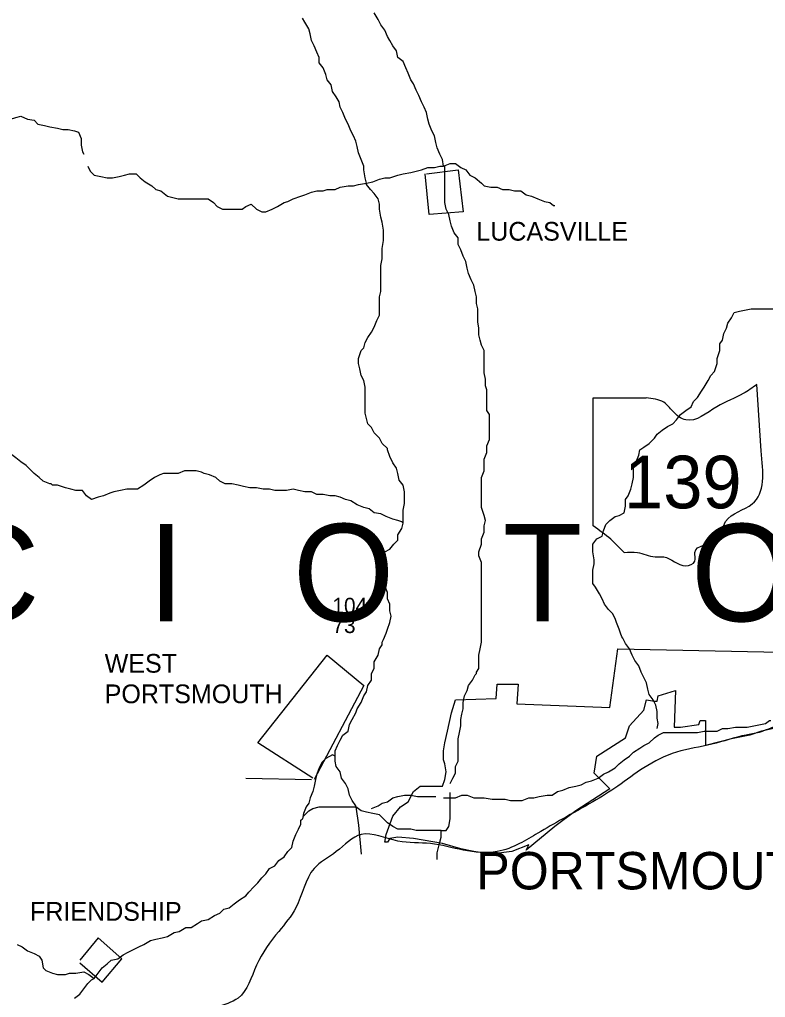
# Model space of a CAD drawing. Extents: x 0 to 34, y 0 to 22.
# Drawn here: x 5.61 to 6.387, y 16.176 to 17.195 of the extents above; entities that cross this region are included whole.
import ezdxf

# ---------------------------------------------------------------- set-up
doc = ezdxf.new("R2010")
doc.units = 0
doc.layers.add('Default', color=7, linetype='Continuous')
doc.layers.add('TR_Turning_Path1', color=7, linetype='Continuous')

msp = doc.modelspace()

# ---------------------------------------------------------------- linework, layer by layer
at = {"layer": 'Default'}
msp.add_line((5.8454, 16.4046), (5.9136, 16.4032), dxfattribs=at)
for points in [[(5.9654, 17.0495), (5.9627, 17.0563), (5.9613, 17.0631), (5.96, 17.0686), (5.9573, 17.074), (5.9545, 17.0795), (5.9518, 17.0863), (5.9491, 17.0917), (5.9463, 17.0985), (5.9436, 17.104), (5.9423, 17.1095), (5.9395, 17.1149), (5.9354, 17.1204), (5.9341, 17.1272), (5.93, 17.1326), (5.9286, 17.1381), (5.9259, 17.1449), (5.9218, 17.1504), (5.9218, 17.1558), (5.9191, 17.1613), (5.9163, 17.1681), (5.9136, 17.1735), (5.9123, 17.1804), (5.9109, 17.1858), (5.9068, 17.1926), (5.9041, 17.1967)], [(6.0513, 17.0426), (6.05, 17.0495), (6.0472, 17.0549), (6.0445, 17.0617), (6.0431, 17.0672), (6.0418, 17.074), (6.0391, 17.0795), (6.0363, 17.0863), (6.035, 17.0917), (6.0336, 17.0985), (6.0309, 17.104), (6.0281, 17.1095), (6.0254, 17.1163), (6.0227, 17.1217), (6.02, 17.1285), (6.0172, 17.1326), (6.0145, 17.1395), (6.0118, 17.1449), (6.0091, 17.1517), (6.0036, 17.1558), (6.0022, 17.1626), (5.9982, 17.1681), (5.9954, 17.1735), (5.9927, 17.1776), (5.99, 17.1844), (5.9859, 17.1899), (5.9832, 17.1954), (5.9791, 17.2022)], [(5.5809, 17.0904), (5.5864, 17.0904), (5.5932, 17.0904), (5.6, 17.0917), (5.6055, 17.0931), (5.6109, 17.0945), (5.6178, 17.0917), (5.6246, 17.0904), (5.6287, 17.0863), (5.6355, 17.0849), (5.6409, 17.0836), (5.6491, 17.0822), (5.6546, 17.0808), (5.66, 17.0808), (5.6668, 17.0795), (5.6709, 17.0781), (5.6737, 17.0713), (5.6737, 17.0645), (5.675, 17.0576), (5.6764, 17.0549), (5.6764, 17.0549)], [(5.6805, 17.0426), (5.6832, 17.0372), (5.6873, 17.0331), (5.6941, 17.0317), (5.7009, 17.0304), (5.7064, 17.0304), (5.7132, 17.0317), (5.7187, 17.0331), (5.7241, 17.0345), (5.7309, 17.0345), (5.735, 17.0304), (5.7405, 17.0263), (5.7473, 17.0222), (5.7514, 17.0181), (5.7568, 17.0167), (5.7636, 17.0113), (5.7691, 17.0099), (5.7746, 17.0086), (5.7814, 17.0086), (5.7882, 17.0086), (5.7936, 17.0086), (5.7991, 17.0086), (5.8059, 17.0086), (5.8114, 17.0045), (5.8155, 17.0004), (5.8209, 16.9977), (5.8277, 16.9977)], [(5.9709, 17.0249), (5.9695, 17.0304), (5.9682, 17.0386), (5.9682, 17.0426), (5.9654, 17.0495), (5.9654, 17.0495)], [(5.9709, 17.0249), (5.9777, 17.0263), (5.9845, 17.029), (5.99, 17.0304), (5.9954, 17.0304), (6.0036, 17.0331), (6.0091, 17.0345), (6.0172, 17.0358), (6.0227, 17.0372), (6.0281, 17.0386), (6.035, 17.0413), (6.0418, 17.0413), (6.0472, 17.0426), (6.0513, 17.0426)], [(6.0513, 17.0426), (6.0581, 17.0454), (6.0636, 17.0454), (6.0691, 17.0413), (6.0745, 17.0386), (6.0786, 17.0331), (6.084, 17.0304), (6.0909, 17.0249), (6.0936, 17.0222), (6.1004, 17.0208), (6.1072, 17.0208), (6.1127, 17.0181), (6.1195, 17.0181), (6.125, 17.0167), (6.1318, 17.0167), (6.1372, 17.0127), (6.1427, 17.0113), (6.1495, 17.0086), (6.1563, 17.0058), (6.1618, 17.0045), (6.1659, 17.0017), (6.1672, 17.0017)], [(6.0936, 16.8436), (6.0936, 16.8504), (6.0909, 16.8559), (6.0895, 16.8613), (6.0881, 16.8668), (6.0881, 16.8736), (6.0868, 16.8804), (6.0868, 16.8872), (6.0868, 16.894), (6.0854, 16.8995), (6.0854, 16.9063), (6.084, 16.9118), (6.0827, 16.9186), (6.08, 16.924), (6.0772, 16.9308), (6.0759, 16.9363), (6.0745, 16.9431), (6.0718, 16.9486), (6.0691, 16.9554), (6.0663, 16.9608), (6.0663, 16.9677), (6.0622, 16.9731), (6.0595, 16.9799), (6.0581, 16.9854), (6.0568, 16.9922), (6.0541, 16.9977), (6.0527, 17.0045), (6.0527, 17.0086), (6.0527, 17.0167), (6.0527, 17.0222), (6.0527, 17.029), (6.0527, 17.0358), (6.0527, 17.0413), (6.0527, 17.0426), (6.0513, 17.0426)], [(6.0336, 17.0345), (6.0663, 17.0386), (6.0718, 16.9949), (6.0363, 16.9922), (6.0322, 17.0345)], [(5.8277, 16.9977), (5.8332, 16.9977), (5.8414, 16.9977), (5.8454, 17.0004), (5.8509, 17.0031), (5.8564, 16.9977), (5.8618, 16.9949), (5.8659, 16.9949), (5.8727, 16.9977), (5.8782, 17.0004), (5.885, 17.0045), (5.8891, 17.0058), (5.8945, 17.0086), (5.9027, 17.0113), (5.9068, 17.0127), (5.9136, 17.0154), (5.9191, 17.0167), (5.9259, 17.0167), (5.93, 17.0181), (5.9382, 17.0181), (5.9436, 17.0208), (5.9518, 17.0222), (5.9573, 17.0222), (5.9627, 17.0236), (5.9709, 17.0249), (5.9709, 17.0249)], [(5.9682, 16.8531), (5.9695, 16.8586), (5.9722, 16.864), (5.9763, 16.8695), (5.9791, 16.8749), (5.9818, 16.8818), (5.9845, 16.8872), (5.9845, 16.894), (5.9845, 16.8995), (5.9845, 16.9063), (5.9859, 16.9118), (5.9859, 16.9186), (5.9859, 16.9254), (5.9859, 16.9322), (5.9859, 16.939), (5.9872, 16.9458), (5.9872, 16.9513), (5.9872, 16.9568), (5.9886, 16.9649), (5.9886, 16.9718), (5.9886, 16.9758), (5.9872, 16.984), (5.9859, 16.9895), (5.9845, 16.9977), (5.9845, 17.0031), (5.9832, 17.0086), (5.9791, 17.014), (5.975, 17.0181), (5.9709, 17.0236), (5.9709, 17.0249), (5.9709, 17.0249)], [(6.3363, 16.8368), (6.3363, 16.8422), (6.339, 16.8504), (6.339, 16.8572), (6.3417, 16.8613), (6.3431, 16.8681), (6.3458, 16.8736), (6.3472, 16.879), (6.3513, 16.8845), (6.354, 16.8899), (6.3595, 16.8913), (6.3663, 16.8927), (6.3717, 16.894), (6.3785, 16.894), (6.3854, 16.894), (6.3908, 16.894), (6.3963, 16.894), (6.4031, 16.8913), (6.4072, 16.8886), (6.4126, 16.8872), (6.4126, 16.8872)], [(5.9927, 16.7481), (5.9872, 16.7536), (5.9845, 16.7591), (5.9791, 16.7645), (5.9763, 16.77), (5.9722, 16.7741), (5.9709, 16.7795), (5.9695, 16.785), (5.9695, 16.7931), (5.9695, 16.8), (5.9695, 16.8054), (5.9695, 16.8122), (5.9682, 16.819), (5.9654, 16.8245), (5.9641, 16.8313), (5.9627, 16.8368), (5.9627, 16.8422), (5.9654, 16.8504), (5.9682, 16.8531)], [(6.0909, 16.6868), (6.0909, 16.6936), (6.0909, 16.6991), (6.0909, 16.7059), (6.0909, 16.7113), (6.0909, 16.7182), (6.0936, 16.725), (6.0936, 16.7304), (6.0936, 16.7372), (6.0963, 16.7441), (6.0963, 16.7509), (6.099, 16.7577), (6.099, 16.7631), (6.099, 16.7686), (6.099, 16.7768), (6.099, 16.7836), (6.0963, 16.7877), (6.0963, 16.7959), (6.0963, 16.8013), (6.0963, 16.8095), (6.095, 16.8136), (6.095, 16.8204), (6.0936, 16.8272), (6.0936, 16.834), (6.0936, 16.8409), (6.0936, 16.8422), (6.0936, 16.8436)], [(6.2517, 16.7345), (6.2545, 16.7413), (6.2558, 16.7468), (6.2599, 16.7495), (6.2654, 16.7536), (6.2708, 16.7591), (6.2736, 16.7631), (6.279, 16.7672), (6.2845, 16.7713), (6.2899, 16.7741), (6.294, 16.7781), (6.2981, 16.7836), (6.3036, 16.7877), (6.309, 16.7918), (6.3117, 16.7972), (6.3158, 16.8013), (6.3199, 16.8081), (6.3226, 16.8122), (6.3267, 16.819), (6.3295, 16.8245), (6.3336, 16.8286), (6.3363, 16.8368), (6.3363, 16.8368)], [(6.382, 16.7458), (6.3774, 16.8148)], [(6.2071, 16.6675), (6.2071, 16.801), (6.2623, 16.801)], [(5.6437, 16.71), (5.6423, 16.7113), (5.6409, 16.7113), (5.6341, 16.7141), (5.63, 16.7182), (5.6246, 16.7222), (5.6205, 16.7263), (5.6164, 16.7304), (5.6109, 16.7345), (5.6055, 16.7386), (5.6, 16.7427), (5.5946, 16.7468), (5.5905, 16.7481), (5.5837, 16.7522), (5.5782, 16.7536), (5.5728, 16.7563), (5.5673, 16.7604)], [(6.0091, 16.6704), (6.0091, 16.6773), (6.0091, 16.6841), (6.0104, 16.6909), (6.0104, 16.6977), (6.0104, 16.7032), (6.0091, 16.71), (6.005, 16.7154), (6.0036, 16.7222), (6.0022, 16.7277), (5.9982, 16.7332), (5.9954, 16.74), (5.9927, 16.7468), (5.9927, 16.7468), (5.9927, 16.7481)], [(6.2068, 16.6486), (6.2108, 16.6541), (6.2163, 16.6568), (6.2177, 16.6623), (6.2204, 16.6691), (6.2245, 16.6732), (6.2299, 16.6773), (6.234, 16.6786), (6.2395, 16.6813), (6.2408, 16.6882), (6.2408, 16.695), (6.2436, 16.6991), (6.2463, 16.7059), (6.2477, 16.7113), (6.249, 16.7182), (6.249, 16.7222), (6.249, 16.7304), (6.2517, 16.7332), (6.2517, 16.7345)], [(5.8018, 16.7222), (5.8018, 16.7222), (5.7991, 16.7236), (5.7936, 16.725), (5.7868, 16.725), (5.7814, 16.725), (5.7746, 16.7222), (5.7664, 16.7222), (5.7596, 16.7222), (5.7555, 16.7209), (5.75, 16.7182), (5.7446, 16.7141), (5.7391, 16.71), (5.7323, 16.7059), (5.7268, 16.7059), (5.7214, 16.7059), (5.7146, 16.7045), (5.7077, 16.7032), (5.7037, 16.7018), (5.6968, 16.6991), (5.6914, 16.6977), (5.6846, 16.695), (5.6791, 16.6991), (5.675, 16.7045), (5.6682, 16.7045), (5.6628, 16.7059), (5.6573, 16.7072), (5.6491, 16.71), (5.6437, 16.71)], [(6.0091, 16.6704), (6.0077, 16.6718), (6.0036, 16.6732), (5.9982, 16.6745), (5.9913, 16.6773), (5.9859, 16.68), (5.9791, 16.6813), (5.9736, 16.6854), (5.9682, 16.6868), (5.9613, 16.6895), (5.9545, 16.6936), (5.9491, 16.695), (5.9436, 16.6977), (5.9382, 16.6991), (5.9327, 16.6991), (5.9259, 16.7004), (5.9191, 16.7004), (5.9136, 16.7032), (5.9068, 16.7032), (5.9, 16.7045), (5.8945, 16.7059), (5.8877, 16.7045), (5.8809, 16.7045), (5.8754, 16.7045), (5.87, 16.7059), (5.8632, 16.7059), (5.8564, 16.7072), (5.8495, 16.7072), (5.8427, 16.7086), (5.8373, 16.71), (5.8305, 16.7113), (5.8236, 16.7113), (5.8182, 16.7141), (5.8141, 16.7182), (5.8073, 16.7209), (5.8018, 16.7222)], [(6.0854, 16.515), (6.0881, 16.5191), (6.0881, 16.5259), (6.0881, 16.5327), (6.0895, 16.5395), (6.0909, 16.5464), (6.0909, 16.5518), (6.0909, 16.5586), (6.0909, 16.5641), (6.0909, 16.5709), (6.0909, 16.5777), (6.0909, 16.5832), (6.0909, 16.5914), (6.0909, 16.5968), (6.0909, 16.6036), (6.0909, 16.6077), (6.0909, 16.6159), (6.0909, 16.6214), (6.0909, 16.6295), (6.0881, 16.6363), (6.0881, 16.6404), (6.0909, 16.6486), (6.0909, 16.6541), (6.0936, 16.6609), (6.0936, 16.6677), (6.095, 16.6732), (6.0936, 16.6786), (6.0909, 16.6868)], [(5.9872, 16.5436), (5.9872, 16.5464), (5.9886, 16.5491), (5.9913, 16.5559), (5.9927, 16.56), (5.9954, 16.5668), (5.9968, 16.5736), (5.9954, 16.5791), (5.9954, 16.5859), (5.9927, 16.5914), (5.9927, 16.5982), (5.99, 16.605), (5.9886, 16.6104), (5.9872, 16.6159), (5.9859, 16.6227), (5.9859, 16.6295), (5.9859, 16.6363), (5.99, 16.6404), (5.9954, 16.6432), (5.9995, 16.6486), (6.0036, 16.6527), (6.0036, 16.6582), (6.0077, 16.665), (6.0091, 16.6704)], [(5.9872, 16.5436), (5.9872, 16.5464), (5.9886, 16.5491), (5.9913, 16.5559), (5.9927, 16.56), (5.9954, 16.5668), (5.9968, 16.5736), (5.9954, 16.5791), (5.9954, 16.5859), (5.9927, 16.5914), (5.9927, 16.5982), (5.99, 16.605), (5.9886, 16.6104), (5.9872, 16.6159), (5.9859, 16.6227), (5.9859, 16.6295), (5.9859, 16.6363), (5.99, 16.6404), (5.9954, 16.6432), (5.9995, 16.6486), (6.0036, 16.6527), (6.0036, 16.6582), (6.0077, 16.665), (6.0091, 16.6704)], [(6.2354, 16.5559), (6.234, 16.56), (6.2313, 16.5668), (6.2299, 16.5709), (6.2272, 16.5764), (6.2231, 16.5804), (6.219, 16.5859), (6.2163, 16.5914), (6.2136, 16.5968), (6.2095, 16.6036), (6.2068, 16.6077), (6.2068, 16.6145), (6.2068, 16.6214), (6.2081, 16.6282), (6.2081, 16.6323), (6.2068, 16.6404), (6.2068, 16.6459), (6.2068, 16.6486)], [(6.2736, 16.4564), (6.2749, 16.4618), (6.2736, 16.4673), (6.2736, 16.4741), (6.2722, 16.4809), (6.2695, 16.4864), (6.2654, 16.4918), (6.264, 16.4973), (6.2627, 16.5041), (6.2599, 16.5096), (6.2572, 16.515), (6.2545, 16.5218), (6.2504, 16.5273), (6.2477, 16.5327), (6.2449, 16.5395), (6.2408, 16.545), (6.2381, 16.5505), (6.2368, 16.5518), (6.2354, 16.5559)], [(5.9382, 16.4277), (5.9382, 16.4291), (5.9382, 16.4332), (5.9409, 16.4387), (5.9436, 16.4441), (5.9463, 16.4496), (5.9518, 16.4537), (5.9532, 16.4605), (5.9559, 16.4659), (5.96, 16.4727), (5.9613, 16.4768), (5.9654, 16.4836), (5.9682, 16.4905), (5.9709, 16.4946), (5.9722, 16.5014), (5.9763, 16.5068), (5.9763, 16.5136), (5.9791, 16.5191), (5.9791, 16.5259), (5.9832, 16.5327), (5.9845, 16.5395), (5.9872, 16.5436)], [(5.9382, 16.4277), (5.9382, 16.4291), (5.9382, 16.4332), (5.9409, 16.4387), (5.9436, 16.4441), (5.9463, 16.4496), (5.9518, 16.4537), (5.9532, 16.4605), (5.9559, 16.4659), (5.96, 16.4727), (5.9613, 16.4768), (5.9654, 16.4836), (5.9682, 16.4905), (5.9709, 16.4946), (5.9722, 16.5014), (5.9763, 16.5068), (5.9763, 16.5136), (5.9791, 16.5191), (5.9791, 16.5259), (5.9832, 16.5327), (5.9845, 16.5395), (5.9872, 16.5436)], [(5.915, 16.4046), (5.8577, 16.4414), (5.93, 16.5327), (5.9682, 16.5014), (5.9163, 16.4032)], [(5.9913, 16.3459), (5.9982, 16.365), (6.0063, 16.3746), (6.0145, 16.38), (6.02, 16.3909), (6.0268, 16.3964), (6.05, 16.3964), (6.0527, 16.4032), (6.0541, 16.4114), (6.0527, 16.4196), (6.0513, 16.4237), (6.0513, 16.4332), (6.0527, 16.4414), (6.0554, 16.4537), (6.0595, 16.4727), (6.0636, 16.4864), (6.1059, 16.4877), (6.1072, 16.5027), (6.129, 16.5027), (6.1277, 16.4823), (6.2245, 16.4782), (6.2327, 16.5395), (6.4863, 16.5341)], [(6.0663, 16.4264), (6.0663, 16.4332), (6.0663, 16.44), (6.0663, 16.4455), (6.0677, 16.4523), (6.0691, 16.4591), (6.0691, 16.4659), (6.0704, 16.4714), (6.0718, 16.4768), (6.0718, 16.4836), (6.0731, 16.4905), (6.0759, 16.4959), (6.0772, 16.5014), (6.0813, 16.5068), (6.084, 16.5123), (6.0854, 16.5136), (6.0854, 16.515)], [(6.2245, 16.3937), (6.2081, 16.41), (6.2108, 16.4277), (6.2408, 16.4468), (6.2449, 16.4591), (6.2599, 16.4755), (6.2627, 16.4864), (6.2708, 16.485), (6.2736, 16.485), (6.2749, 16.4905), (6.2927, 16.4959), (6.2913, 16.4577), (6.2981, 16.4577), (6.3172, 16.4605), (6.3186, 16.4646), (6.324, 16.4646), (6.324, 16.4387)], [(6.3036, 16.4523), (6.309, 16.4523), (6.3158, 16.4523), (6.3226, 16.4537), (6.3295, 16.4537), (6.3363, 16.4537), (6.3417, 16.4564), (6.3472, 16.4564), (6.3554, 16.4577), (6.3608, 16.4577), (6.3676, 16.4577), (6.3745, 16.4591), (6.3813, 16.4605), (6.3867, 16.4618), (6.3908, 16.4646), (6.3922, 16.4646)], [(6.1822, 16.395), (6.189, 16.3964), (6.1945, 16.3977), (6.1999, 16.4005), (6.2054, 16.4018), (6.2122, 16.4046), (6.2177, 16.4087), (6.2231, 16.4114), (6.2299, 16.4155), (6.234, 16.4196), (6.2395, 16.4237), (6.2449, 16.4277), (6.249, 16.4318), (6.2558, 16.4359), (6.2599, 16.4387), (6.2654, 16.4414), (6.2708, 16.4468), (6.2749, 16.4496), (6.2804, 16.4523), (6.2804, 16.4523)], [(6.2804, 16.4523), (6.2872, 16.4523), (6.294, 16.4523), (6.3008, 16.4523), (6.3036, 16.4523)], [(6.414, 16.4605), (6.3826, 16.4537), (6.3704, 16.4496), (6.3513, 16.4455), (6.324, 16.4387)], [(5.9382, 16.4277), (5.9382, 16.4277), (5.9354, 16.4291), (5.9286, 16.425), (5.9245, 16.4209), (5.9218, 16.4155), (5.9191, 16.4087), (5.9177, 16.4032), (5.9163, 16.3964), (5.915, 16.3909), (5.9123, 16.3841), (5.9109, 16.3787)], [(5.96, 16.3746), (5.96, 16.3759), (5.9559, 16.3814), (5.9532, 16.3868), (5.9518, 16.3937), (5.9491, 16.3991), (5.945, 16.4046), (5.9436, 16.4114), (5.9395, 16.4168), (5.9382, 16.4223), (5.9382, 16.4277)], [(5.96, 16.3746), (5.96, 16.3759), (5.9559, 16.3814), (5.9532, 16.3868), (5.9518, 16.3937), (5.9491, 16.3991), (5.945, 16.4046), (5.9436, 16.4114), (5.9395, 16.4168), (5.9382, 16.4223), (5.9382, 16.4277)], [(6.0581, 16.3991), (6.0609, 16.4046), (6.0636, 16.41), (6.0636, 16.4168), (6.0663, 16.4223), (6.0663, 16.4264)], [(6.2245, 16.3937), (6.189, 16.3705), (6.1672, 16.3541), (6.1372, 16.3296), (6.1399, 16.335), (6.1222, 16.3282), (6.1004, 16.3255), (6.0827, 16.3282), (6.0691, 16.3309), (6.05, 16.3364), (6.02, 16.3418), (6.0036, 16.3432), (5.9954, 16.3418), (5.9927, 16.3378)], [(6.1454, 16.3841), (6.1509, 16.3855), (6.159, 16.3868), (6.1645, 16.3868), (6.1699, 16.3909), (6.1754, 16.3923), (6.1822, 16.395)], [(5.9763, 16.3732), (5.9832, 16.3759), (5.9872, 16.3787), (5.9927, 16.38), (5.9982, 16.3841), (6.0036, 16.3855), (6.0104, 16.3868), (6.0172, 16.3868), (6.0241, 16.3855), (6.0295, 16.3855), (6.0363, 16.3855), (6.0418, 16.3855), (6.0431, 16.3855)], [(6.0486, 16.35), (6.0541, 16.35), (6.0568, 16.3541), (6.0581, 16.3623), (6.0581, 16.3678), (6.0581, 16.3746), (6.0581, 16.38), (6.0581, 16.3841)], [(6.0513, 16.3841), (6.0581, 16.3841), (6.0581, 16.3841)], [(6.0581, 16.3841), (6.0581, 16.3896)], [(6.0581, 16.3841), (6.0636, 16.3841), (6.0704, 16.3868), (6.0759, 16.3868), (6.0827, 16.3841), (6.0881, 16.3841), (6.0936, 16.3841), (6.1018, 16.3828), (6.1072, 16.3828), (6.1154, 16.3828), (6.1209, 16.3814), (6.1277, 16.3814), (6.1331, 16.3814), (6.1399, 16.3841), (6.1427, 16.3841), (6.1454, 16.3841)], [(5.9109, 16.3787), (5.9082, 16.3746), (5.9054, 16.3678), (5.9041, 16.3623)], [(5.9054, 16.365), (5.9109, 16.3705), (5.915, 16.3732), (5.9218, 16.3746), (5.9286, 16.3746), (5.9354, 16.3746), (5.9395, 16.3746), (5.9463, 16.3746), (5.9532, 16.3746), (5.96, 16.3746), (5.96, 16.3746)], [(6.0486, 16.35), (6.0472, 16.35), (6.0431, 16.35), (6.0363, 16.35), (6.0295, 16.35), (6.0227, 16.35), (6.0172, 16.3514), (6.0104, 16.3514), (6.0036, 16.3514), (5.9982, 16.3541), (5.9927, 16.3582), (5.9886, 16.3623), (5.9845, 16.3664), (5.9777, 16.3678), (5.9709, 16.3691), (5.9654, 16.3705), (5.96, 16.3746)], [(6.0486, 16.35), (6.0472, 16.35), (6.0431, 16.35), (6.0363, 16.35), (6.0295, 16.35), (6.0227, 16.35), (6.0172, 16.3514), (6.0104, 16.3514), (6.0036, 16.3514), (5.9982, 16.3541), (5.9927, 16.3582), (5.9886, 16.3623), (5.9845, 16.3664), (5.9777, 16.3678), (5.9709, 16.3691), (5.9654, 16.3705), (5.96, 16.3746)], [(5.96, 16.3746), (5.9627, 16.3555), (5.9654, 16.3255)], [(5.7991, 16.256), (5.8059, 16.2573), (5.8127, 16.2614), (5.8182, 16.2641), (5.8223, 16.2682), (5.8277, 16.2696), (5.8332, 16.2737), (5.8386, 16.2778), (5.8454, 16.2819), (5.8482, 16.2859), (5.8536, 16.2914), (5.8577, 16.2955), (5.8618, 16.3009), (5.8659, 16.305), (5.87, 16.3105), (5.8754, 16.3132), (5.8795, 16.3187), (5.885, 16.3228), (5.8891, 16.3282), (5.8932, 16.3323), (5.8945, 16.3391), (5.8973, 16.3459), (5.9, 16.3514), (5.9027, 16.3568), (5.9027, 16.3609), (5.9041, 16.3623)], [(6.0472, 16.3378), (6.0486, 16.3432), (6.0486, 16.35)], [(5.9927, 16.3378), (5.99, 16.3378), (5.9913, 16.3459)], [(6.0445, 16.32), (6.0445, 16.3269), (6.0459, 16.3323), (6.0472, 16.3378), (6.0472, 16.3378)], [(5.6873, 16.196), (5.6914, 16.2014), (5.6955, 16.2069), (5.7009, 16.211), (5.705, 16.2151), (5.7118, 16.2164), (5.7173, 16.2205), (5.7227, 16.2232), (5.7282, 16.226), (5.7336, 16.2287), (5.7391, 16.2314), (5.7459, 16.2355), (5.7514, 16.2369), (5.7582, 16.2382), (5.7636, 16.2396), (5.7705, 16.2437), (5.7759, 16.245), (5.7827, 16.2491), (5.7882, 16.2491), (5.795, 16.2532), (5.7991, 16.256), (5.7991, 16.256)], [(5.6723, 16.2123), (5.6955, 16.1919), (5.7159, 16.2164), (5.6914, 16.2382), (5.6723, 16.2151)], [(5.6069, 16.2314), (5.6123, 16.2287), (5.6178, 16.2246), (5.6246, 16.2219), (5.63, 16.2191), (5.6328, 16.2151), (5.6341, 16.2069), (5.6368, 16.2041), (5.6437, 16.2014), (5.6491, 16.2001), (5.6573, 16.2001), (5.6614, 16.2014), (5.6682, 16.2014), (5.6764, 16.2028), (5.6818, 16.2001), (5.6873, 16.196)], [(5.6668, 16.1755), (5.6723, 16.1796), (5.6764, 16.1851), (5.6805, 16.1905), (5.6846, 16.1946), (5.6873, 16.196), (5.6873, 16.196)]]:
    msp.add_lwpolyline(points, dxfattribs=at)
for points in [[(6.3774, 16.8148), (6.3635, 16.8056), (6.3359, 16.7918), (6.3037, 16.778), (6.2899, 16.7872), (6.2807, 16.7964), (6.2623, 16.801)], [(6.2393, 16.6399), (6.2531, 16.6399), (6.2715, 16.6353), (6.2807, 16.6353), (6.3037, 16.6261), (6.3129, 16.6307), (6.3129, 16.6399), (6.3359, 16.6537), (6.3451, 16.6721), (6.3728, 16.6905), (6.382, 16.7458)], [(6.2393, 16.6399), (6.2255, 16.6537), (6.2071, 16.6675)], [(6.6853, 15.6179), (6.6553, 15.637), (6.6308, 15.656), (6.5994, 15.6806), (6.579, 15.7174), (6.5653, 15.7529), (6.5531, 15.7842), (6.5435, 15.8306), (6.5381, 15.8701), (6.5381, 15.9124), (6.5381, 15.9505), (6.5353, 16.0024), (6.5217, 16.0433), (6.5108, 16.0773), (6.4944, 16.1033), (6.4781, 16.1223), (6.4699, 16.1496), (6.4699, 16.1919), (6.4835, 16.2273), (6.4931, 16.2696), (6.4931, 16.3132), (6.4863, 16.3555), (6.4835, 16.3964), (6.4672, 16.4264), (6.4494, 16.4427), (6.4222, 16.4577), (6.4058, 16.4605), (6.3799, 16.4523), (6.3663, 16.4496), (6.3308, 16.44), (6.294, 16.4318), (6.2599, 16.4155), (6.2327, 16.3964), (6.2068, 16.38), (6.1754, 16.3623), (6.1495, 16.3473), (6.1304, 16.3364), (6.1072, 16.3282), (6.0718, 16.3296), (6.0377, 16.3364), (6.0036, 16.3391), (5.9654, 16.3459), (5.9395, 16.3282), (5.9163, 16.3105), (5.8973, 16.2696), (5.8795, 16.245), (5.8564, 16.2096), (5.8373, 16.1755), (5.8141, 16.166), (5.7746, 16.1496), (5.7418, 16.1332), (5.7009, 16.121), (5.6737, 16.106), (5.6368, 16.0896), (5.615, 16.0596), (5.6028, 16.0351), (5.5891, 15.9996), (5.5796, 15.9655), (5.5769, 15.9246), (5.5455, 15.896), (5.5114, 15.8701), (5.4637, 15.8469), (5.4132, 15.8469), (5.3723, 15.8387), (5.3273, 15.8387), (5.2837, 15.8442), (5.2428, 15.8633), (5.2169, 15.881), (5.1828, 15.8878), (5.1569, 15.8892), (5.1392, 15.8728), (5.1051, 15.8619), (5.0819, 15.8442)]]:
    msp.add_spline(points, degree=3, dxfattribs=at)

# ---------------------------------------------------------------- texts
for s, height, p in [('LUCASVILLE', 0.0195, (6.0854, 16.9649)), ('139', 0.05486, (6.2393, 16.6859)), ('104', 0.01625, (5.9354, 16.5764)), ('73', 0.01625, (5.9354, 16.5559)), ('WEST', 0.0195, (5.6982, 16.5146)), ('PORTSMOUTH', 0.0195, (5.6982, 16.4828)), ('PORTSMOUTH', 0.039, (6.0854, 16.2887)), ('FRIENDSHIP', 0.0195, (5.6205, 16.256))]:
    msp.add_text(s, height=height, dxfattribs=at).set_placement(p)
at = {"layer": 'TR_Turning_Path1'}
msp.add_text('S   C   I   O   T   O', height=0.101489, dxfattribs=at).set_placement((5.3287, 16.5682))

doc.saveas('drawing.dxf')
